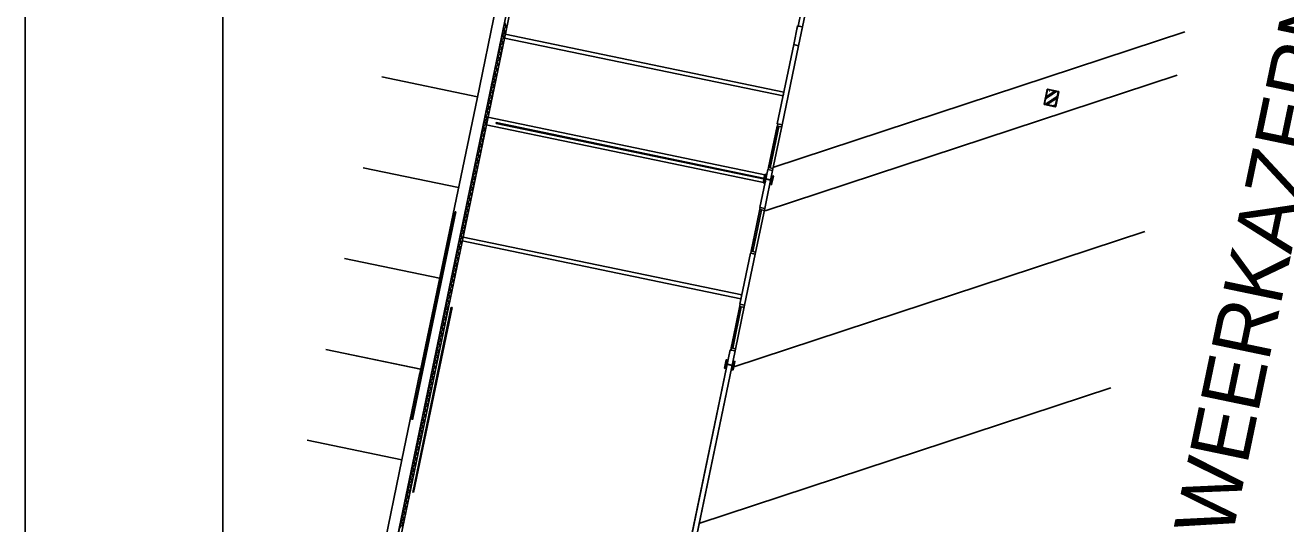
# Model space of a CAD drawing. Extents: x 81065 to 81486, y 452384 to 452681.
# Drawn here: x 81065.21 to 81097.13, y 452550.49 to 452563.13 of the extents above; entities that cross this region are included whole.
import ezdxf

# ---------------------------------------------------------------- set-up
doc = ezdxf.new("R2010")
doc.units = 0
for name, color, linetype in [('B-BH-AL-TOPOGRAFIE_STRAATNAAM-S', 7, 'Continuous'), ('B-BH-VH-KANTOPSLUITING-GV', 7, 'Continuous'), ('X-XX-AL-TEKENBLAD_KADER-G', 7, 'Continuous'), ('X-XX-AL-TEKENBLAD_KADER_AFSNIJMARKERING-G', 7, 'Continuous'), ('X-XX-AL-TEKENBLAD_VIEWPORT-G', 7, 'Continuous')]:
    doc.layers.add(name, color=color, linetype=linetype)

msp = doc.modelspace()

# ---------------------------------------------------------------- linework, layer by layer
at = {"layer": 'B-BH-VH-KANTOPSLUITING-GV'}
for p, q in [((81080.767, 452579.66), (81071.926, 452537.068)), ((81085.024, 452564.266), (81084.783, 452563.107)), ((81077.52, 452564.024), (81073.834, 452546.276)), ((81073.912, 452546.26), (81077.598, 452564.008)), ((81085.135, 452564.243), (81084.895, 452563.084)), ((81076.654, 452561.265), (81077.142, 452563.615)), ((81077.279, 452562.863), (81077.385, 452562.983)), ((81077.307, 452563.001), (81077.414, 452563.12)), ((81077.371, 452562.915), (81077.321, 452563.067)), ((81077.4, 452563.052), (81077.349, 452563.204)), ((81084.772, 452563.109), (81084.674, 452562.636)), ((81084.746, 452562.982), (81084.768, 452563.09)), ((81084.895, 452563.084), (81084.772, 452563.109)), ((81084.895, 452563.084), (81084.783, 452563.107)), ((81084.796, 452562.61), (81084.895, 452563.084)), ((81084.868, 452562.957), (81084.891, 452563.064)), ((81077.222, 452562.589), (81077.328, 452562.709)), ((81077.25, 452562.726), (81077.357, 452562.846)), ((81077.314, 452562.641), (81077.264, 452562.793)), ((81077.343, 452562.778), (81077.292, 452562.93)), ((81077.368, 452562.901), (81077.348, 452562.803)), ((81077.348, 452562.803), (81084.404, 452561.337)), ((81084.425, 452561.435), (81077.368, 452562.901)), ((81084.146, 452559.522), (81094.574, 452562.962)), ((81077.165, 452562.315), (81077.271, 452562.435)), ((81077.229, 452562.229), (81077.179, 452562.381)), ((81077.193, 452562.452), (81077.3, 452562.572)), ((81077.257, 452562.367), (81077.207, 452562.518)), ((81077.286, 452562.504), (81077.236, 452562.656)), ((81084.674, 452562.636), (81084.257, 452560.629)), ((81084.38, 452560.603), (81084.796, 452562.61)), ((81077.079, 452561.904), (81077.186, 452562.023)), ((81077.108, 452562.041), (81077.214, 452562.16)), ((81077.172, 452561.955), (81077.122, 452562.107)), ((81077.136, 452562.178), (81077.243, 452562.297)), ((81077.2, 452562.092), (81077.15, 452562.244)), ((81076.664, 452561.314), (81074.243, 452561.817)), ((81074.243, 452561.817), (81076.664, 452561.314)), ((81077.022, 452561.63), (81077.129, 452561.749)), ((81077.051, 452561.767), (81077.157, 452561.886)), ((81077.115, 452561.681), (81077.065, 452561.833)), ((81077.143, 452561.818), (81077.093, 452561.97)), ((81083.954, 452558.42), (81094.382, 452561.859)), ((81076.966, 452561.356), (81077.072, 452561.475)), ((81077.029, 452561.27), (81076.979, 452561.422)), ((81076.994, 452561.493), (81077.101, 452561.612)), ((81077.058, 452561.407), (81077.008, 452561.559)), ((81077.086, 452561.544), (81077.036, 452561.696)), ((81084.404, 452561.337), (81084.425, 452561.435)), ((81091.09, 452561.501), (81091.013, 452561.129)), ((81091.026, 452561.133), (81091.101, 452561.493)), ((81091.101, 452561.493), (81091.026, 452561.133)), ((81091.055, 452561.274), (81091.325, 452561.451)), ((81091.064, 452561.315), (81091.283, 452561.459)), ((81091.078, 452561.383), (81091.079, 452561.383)), ((81091.095, 452561.508), (81091.09, 452561.501)), ((81091.102, 452561.509), (81091.095, 452561.508)), ((81091.096, 452561.468), (81091.096, 452561.468)), ((81091.098, 452561.482), (81091.117, 452561.494)), ((81091.101, 452561.493), (81091.103, 452561.495)), ((81091.103, 452561.495), (81091.101, 452561.493)), ((81091.376, 452561.452), (81091.102, 452561.509)), ((81091.103, 452561.495), (81091.106, 452561.496)), ((81091.106, 452561.496), (81091.103, 452561.495)), ((81091.106, 452561.496), (81091.368, 452561.441)), ((81091.368, 452561.441), (81091.106, 452561.496)), ((81091.111, 452561.42), (81091.112, 452561.42)), ((81091.145, 452561.458), (81091.146, 452561.457)), ((81091.161, 452561.41), (81091.161, 452561.41)), ((81091.195, 452561.447), (81091.195, 452561.447)), ((81091.21, 452561.4), (81091.211, 452561.4)), ((81091.244, 452561.437), (81091.245, 452561.437)), ((81091.26, 452561.39), (81091.26, 452561.389)), ((81091.294, 452561.427), (81091.294, 452561.427)), ((81091.371, 452561.437), (81091.296, 452561.076)), ((81091.296, 452561.076), (81091.371, 452561.437)), ((81091.307, 452561.068), (81091.384, 452561.44)), ((81091.343, 452561.416), (81091.344, 452561.416)), ((81091.368, 452561.441), (81091.37, 452561.44)), ((81091.37, 452561.44), (81091.368, 452561.441)), ((81091.37, 452561.44), (81091.371, 452561.437)), ((81091.371, 452561.437), (81091.37, 452561.44)), ((81091.383, 452561.448), (81091.376, 452561.452)), ((81091.384, 452561.44), (81091.383, 452561.448)), ((81076.166, 452558.916), (81076.654, 452561.265)), ((81076.88, 452560.944), (81076.987, 452561.064)), ((81076.909, 452561.081), (81077.015, 452561.201)), ((81076.973, 452560.996), (81076.922, 452561.148)), ((81076.937, 452561.219), (81077.044, 452561.338)), ((81077.001, 452561.133), (81076.951, 452561.285)), ((81091.013, 452561.129), (81091.014, 452561.122)), ((81091.014, 452561.122), (81091.021, 452561.117)), ((81091.021, 452561.117), (81091.295, 452561.06)), ((81091.027, 452561.13), (81091.026, 452561.133)), ((81091.026, 452561.133), (81091.027, 452561.13)), ((81091.029, 452561.128), (81091.027, 452561.13)), ((81091.027, 452561.13), (81091.029, 452561.128)), ((81091.291, 452561.073), (81091.029, 452561.128)), ((81091.029, 452561.128), (81091.291, 452561.073)), ((81091.043, 452561.213), (81091.043, 452561.213)), ((81091.046, 452561.124), (81091.347, 452561.322)), ((81091.058, 452561.166), (81091.059, 452561.166)), ((81091.06, 452561.298), (81091.061, 452561.298)), ((81091.075, 452561.118), (81091.075, 452561.118)), ((81091.076, 452561.251), (81091.077, 452561.251)), ((81091.088, 452561.116), (81091.339, 452561.28)), ((81091.092, 452561.203), (81091.093, 452561.203)), ((81091.094, 452561.336), (81091.094, 452561.335)), ((81091.108, 452561.156), (81091.108, 452561.156)), ((81091.11, 452561.288), (81091.11, 452561.288)), ((81091.124, 452561.108), (81091.125, 452561.108)), ((81091.126, 452561.24), (81091.126, 452561.24)), ((81091.127, 452561.373), (81091.128, 452561.373)), ((81091.142, 452561.193), (81091.142, 452561.193)), ((81091.143, 452561.325), (81091.144, 452561.325)), ((81091.157, 452561.145), (81091.158, 452561.145)), ((81091.159, 452561.278), (81091.16, 452561.278)), ((81091.174, 452561.098), (81091.174, 452561.098)), ((81091.175, 452561.23), (81091.176, 452561.23)), ((81091.177, 452561.362), (81091.178, 452561.362)), ((81091.191, 452561.183), (81091.192, 452561.182)), ((81091.193, 452561.315), (81091.193, 452561.315)), ((81091.207, 452561.135), (81091.208, 452561.135)), ((81091.209, 452561.267), (81091.21, 452561.267)), ((81091.223, 452561.088), (81091.224, 452561.087)), ((81091.225, 452561.22), (81091.225, 452561.22)), ((81091.227, 452561.352), (81091.227, 452561.352)), ((81091.241, 452561.172), (81091.241, 452561.172)), ((81091.242, 452561.305), (81091.243, 452561.305)), ((81091.254, 452561.081), (81091.304, 452561.114)), ((81091.257, 452561.125), (81091.257, 452561.125)), ((81091.258, 452561.257), (81091.259, 452561.257)), ((81091.273, 452561.077), (81091.273, 452561.077)), ((81091.274, 452561.21), (81091.275, 452561.21)), ((81091.276, 452561.342), (81091.277, 452561.342)), ((81091.29, 452561.162), (81091.291, 452561.162)), ((81091.294, 452561.074), (81091.291, 452561.073)), ((81091.291, 452561.073), (81091.294, 452561.074)), ((81091.292, 452561.294), (81091.292, 452561.294)), ((81091.296, 452561.076), (81091.294, 452561.074)), ((81091.294, 452561.074), (81091.296, 452561.076)), ((81091.302, 452561.062), (81091.307, 452561.068)), ((81091.308, 452561.247), (81091.309, 452561.247)), ((81091.309, 452561.379), (81091.31, 452561.379)), ((81091.326, 452561.332), (81091.326, 452561.331)), ((81076.823, 452560.67), (81076.93, 452560.79)), ((81076.852, 452560.807), (81076.958, 452560.927)), ((81076.916, 452560.722), (81076.865, 452560.874)), ((81076.931, 452560.795), (81076.89, 452560.6)), ((81076.944, 452560.859), (81076.894, 452561.011)), ((81083.987, 452559.33), (81076.931, 452560.795)), ((81091.295, 452561.06), (81091.302, 452561.062)), ((81076.766, 452560.396), (81076.873, 452560.516)), ((81076.83, 452560.31), (81076.78, 452560.462)), ((81076.795, 452560.533), (81076.901, 452560.653)), ((81076.859, 452560.447), (81076.809, 452560.599)), ((81076.887, 452560.585), (81076.837, 452560.737)), ((81076.89, 452560.6), (81083.947, 452559.134)), ((81077.14, 452560.65), (81077.138, 452560.64)), ((81077.138, 452560.64), (81083.94, 452559.228)), ((81077.142, 452560.66), (81077.14, 452560.65)), ((81083.942, 452559.237), (81077.14, 452560.65)), ((81077.14, 452560.65), (81083.942, 452559.237)), ((81083.944, 452559.247), (81077.142, 452560.66)), ((81084.268, 452560.627), (81084.027, 452559.467)), ((81084.257, 452560.573), (81084.038, 452559.521)), ((81084.078, 452559.513), (81084.296, 452560.565)), ((81084.38, 452560.603), (81084.139, 452559.444)), ((81084.38, 452560.603), (81084.257, 452560.629)), ((81084.257, 452560.573), (81084.368, 452560.55)), ((81084.296, 452560.565), (81084.257, 452560.573)), ((81084.38, 452560.603), (81084.268, 452560.627)), ((81076.709, 452560.122), (81076.816, 452560.241)), ((81076.773, 452560.036), (81076.723, 452560.188)), ((81076.738, 452560.259), (81076.844, 452560.378)), ((81076.802, 452560.173), (81076.752, 452560.325)), ((81076.624, 452559.711), (81076.73, 452559.83)), ((81076.652, 452559.848), (81076.759, 452559.967)), ((81076.716, 452559.762), (81076.666, 452559.914)), ((81076.681, 452559.985), (81076.787, 452560.104)), ((81076.745, 452559.899), (81076.695, 452560.051)), ((81076.186, 452559.013), (81073.77, 452559.515)), ((81073.77, 452559.515), (81076.186, 452559.013)), ((81076.567, 452559.437), (81076.674, 452559.556)), ((81076.631, 452559.351), (81076.581, 452559.503)), ((81076.595, 452559.574), (81076.702, 452559.693)), ((81076.659, 452559.488), (81076.609, 452559.64)), ((81076.688, 452559.625), (81076.638, 452559.777)), ((81084.016, 452559.47), (81083.817, 452558.51)), ((81084.139, 452559.444), (81084.016, 452559.47)), ((81084.139, 452559.444), (81084.027, 452559.467)), ((81084.038, 452559.521), (81084.15, 452559.498)), ((81084.038, 452559.521), (81084.078, 452559.513)), ((81076.51, 452559.162), (81076.617, 452559.282)), ((81076.574, 452559.077), (81076.524, 452559.229)), ((81076.539, 452559.3), (81076.645, 452559.419)), ((81076.602, 452559.214), (81076.552, 452559.366)), ((81083.943, 452559.349), (81083.899, 452559.134)), ((81083.914, 452559.131), (81083.936, 452559.234)), ((81083.936, 452559.234), (81084.12, 452559.195)), ((81083.938, 452559.243), (81083.959, 452559.346)), ((81084.122, 452559.205), (81083.938, 452559.243)), ((81083.939, 452558.484), (81084.139, 452559.444)), ((81083.94, 452559.228), (81083.942, 452559.237)), ((81083.942, 452559.237), (81083.944, 452559.247)), ((81083.959, 452559.346), (81083.943, 452559.349)), ((81083.947, 452559.134), (81083.987, 452559.33)), ((81084.12, 452559.195), (81084.098, 452559.092)), ((81084.114, 452559.089), (81084.159, 452559.305)), ((81084.143, 452559.308), (81084.122, 452559.205)), ((81084.159, 452559.305), (81084.143, 452559.308)), ((81075.678, 452556.566), (81076.166, 452558.916)), ((81076.425, 452558.751), (81076.531, 452558.871)), ((81076.453, 452558.888), (81076.56, 452559.008)), ((81076.517, 452558.803), (81076.467, 452558.955)), ((81076.482, 452559.025), (81076.588, 452559.145)), ((81076.546, 452558.94), (81076.495, 452559.092)), ((81083.899, 452559.134), (81083.914, 452559.131)), ((81084.098, 452559.092), (81084.114, 452559.089)), ((81076.368, 452558.477), (81076.474, 452558.596)), ((81076.432, 452558.391), (81076.381, 452558.543)), ((81076.396, 452558.614), (81076.503, 452558.734)), ((81076.46, 452558.528), (81076.41, 452558.68)), ((81076.489, 452558.666), (81076.438, 452558.817)), ((81083.939, 452558.484), (81083.817, 452558.51)), ((81076.097, 452558.402), (81075.003, 452553.133)), ((81075.013, 452553.131), (81076.107, 452558.4)), ((81076.107, 452558.4), (81075.013, 452553.131)), ((81075.022, 452553.129), (81076.117, 452558.398)), ((81076.107, 452558.4), (81076.097, 452558.402)), ((81076.117, 452558.398), (81076.107, 452558.4)), ((81076.311, 452558.203), (81076.417, 452558.322)), ((81076.375, 452558.117), (81076.325, 452558.269)), ((81076.339, 452558.34), (81076.446, 452558.459)), ((81076.403, 452558.254), (81076.353, 452558.406)), ((81083.828, 452558.507), (81083.587, 452557.348)), ((81083.817, 452558.454), (81083.598, 452557.402)), ((81083.637, 452557.394), (81083.856, 452558.445)), ((81083.939, 452558.484), (81083.699, 452557.325)), ((81083.817, 452558.454), (81083.928, 452558.43)), ((81083.856, 452558.445), (81083.817, 452558.454)), ((81083.939, 452558.484), (81083.828, 452558.507)), ((81076.225, 452557.792), (81076.332, 452557.911)), ((81076.254, 452557.929), (81076.36, 452558.048)), ((81076.318, 452557.843), (81076.268, 452557.995)), ((81076.282, 452558.066), (81076.389, 452558.185)), ((81076.346, 452557.98), (81076.296, 452558.132)), ((81083.132, 452554.463), (81093.56, 452557.902)), ((81076.168, 452557.518), (81076.275, 452557.637)), ((81076.232, 452557.432), (81076.182, 452557.584)), ((81076.197, 452557.655), (81076.303, 452557.774)), ((81076.261, 452557.569), (81076.211, 452557.721)), ((81076.289, 452557.706), (81076.239, 452557.858)), ((81076.301, 452557.76), (81076.28, 452557.662)), ((81076.28, 452557.662), (81083.337, 452556.197)), ((81083.357, 452556.295), (81076.301, 452557.76)), ((81076.112, 452557.243), (81076.218, 452557.363)), ((81076.175, 452557.158), (81076.125, 452557.31)), ((81076.14, 452557.38), (81076.246, 452557.5)), ((81076.204, 452557.295), (81076.154, 452557.447)), ((81083.576, 452557.35), (81083.307, 452556.056)), ((81083.43, 452556.03), (81083.699, 452557.325)), ((81083.699, 452557.325), (81083.576, 452557.35)), ((81083.699, 452557.325), (81083.587, 452557.348)), ((81083.598, 452557.402), (81083.71, 452557.379)), ((81083.598, 452557.402), (81083.637, 452557.394)), ((81075.708, 452556.713), (81073.298, 452557.214)), ((81073.298, 452557.214), (81075.708, 452556.713)), ((81076.026, 452556.832), (81076.133, 452556.952)), ((81076.055, 452556.969), (81076.161, 452557.089)), ((81076.118, 452556.884), (81076.068, 452557.035)), ((81076.083, 452557.106), (81076.19, 452557.226)), ((81076.147, 452557.021), (81076.097, 452557.173)), ((81075.969, 452556.558), (81076.076, 452556.677)), ((81076.033, 452556.472), (81075.983, 452556.624)), ((81075.998, 452556.695), (81076.104, 452556.814)), ((81076.062, 452556.609), (81076.011, 452556.761)), ((81076.09, 452556.746), (81076.04, 452556.898)), ((81075.19, 452554.216), (81075.678, 452556.566)), ((81075.912, 452556.284), (81076.019, 452556.403)), ((81075.976, 452556.198), (81075.926, 452556.35)), ((81075.941, 452556.421), (81076.047, 452556.54)), ((81076.005, 452556.335), (81075.954, 452556.487)), ((81083.337, 452556.197), (81083.357, 452556.295)), ((81076.002, 452555.978), (81075.028, 452551.287)), ((81075.037, 452551.285), (81076.012, 452555.976)), ((81076.011, 452555.975), (81075.037, 452551.285)), ((81075.047, 452551.283), (81076.021, 452555.973)), ((81075.827, 452555.873), (81075.933, 452555.992)), ((81075.855, 452556.01), (81075.962, 452556.129)), ((81075.919, 452555.924), (81075.869, 452556.076)), ((81075.884, 452556.147), (81075.99, 452556.266)), ((81075.948, 452556.061), (81075.898, 452556.213)), ((81076.012, 452555.976), (81076.002, 452555.978)), ((81076.021, 452555.973), (81076.011, 452555.975)), ((81083.318, 452556.054), (81083.077, 452554.894)), ((81083.307, 452556), (81083.089, 452554.948)), ((81083.128, 452554.94), (81083.346, 452555.992)), ((81083.43, 452556.03), (81083.189, 452554.871)), ((81083.43, 452556.03), (81083.307, 452556.056)), ((81083.307, 452556), (81083.419, 452555.977)), ((81083.346, 452555.992), (81083.307, 452556)), ((81083.43, 452556.03), (81083.318, 452556.054)), ((81075.77, 452555.598), (81075.876, 452555.718)), ((81075.834, 452555.513), (81075.784, 452555.665)), ((81075.798, 452555.736), (81075.905, 452555.855)), ((81075.862, 452555.65), (81075.812, 452555.802)), ((81075.891, 452555.787), (81075.841, 452555.939)), ((81075.713, 452555.324), (81075.819, 452555.444)), ((81075.777, 452555.239), (81075.727, 452555.391)), ((81075.741, 452555.461), (81075.848, 452555.581)), ((81075.805, 452555.376), (81075.755, 452555.528)), ((81075.628, 452554.913), (81075.734, 452555.033)), ((81075.656, 452555.05), (81075.763, 452555.17)), ((81075.72, 452554.964), (81075.67, 452555.116)), ((81075.685, 452555.187), (81075.791, 452555.307)), ((81075.748, 452555.102), (81075.698, 452555.254)), ((81075.222, 452554.413), (81072.825, 452554.911)), ((81072.825, 452554.911), (81075.23, 452554.411)), ((81075.571, 452554.639), (81075.677, 452554.758)), ((81075.635, 452554.553), (81075.584, 452554.705)), ((81075.599, 452554.776), (81075.706, 452554.895)), ((81075.663, 452554.69), (81075.613, 452554.842)), ((81075.691, 452554.827), (81075.641, 452554.979)), ((81083.067, 452554.897), (81081.355, 452546.652)), ((81081.477, 452546.627), (81083.189, 452554.871)), ((81083.189, 452554.871), (81083.067, 452554.897)), ((81083.189, 452554.871), (81083.077, 452554.894)), ((81083.089, 452554.948), (81083.2, 452554.925)), ((81083.089, 452554.948), (81083.128, 452554.94)), ((81075.514, 452554.365), (81075.62, 452554.484)), ((81075.578, 452554.279), (81075.527, 452554.431)), ((81075.542, 452554.502), (81075.649, 452554.621)), ((81075.606, 452554.416), (81075.556, 452554.568)), ((81082.967, 452554.65), (81082.923, 452554.434)), ((81082.923, 452554.434), (81082.938, 452554.431)), ((81082.938, 452554.431), (81082.96, 452554.534)), ((81082.96, 452554.534), (81083.144, 452554.496)), ((81082.962, 452554.543), (81082.983, 452554.646)), ((81083.146, 452554.505), (81082.962, 452554.543)), ((81082.983, 452554.646), (81082.967, 452554.65)), ((81083.144, 452554.496), (81083.122, 452554.393)), ((81083.122, 452554.393), (81083.138, 452554.389)), ((81083.138, 452554.389), (81083.183, 452554.605)), ((81083.167, 452554.608), (81083.146, 452554.505)), ((81083.183, 452554.605), (81083.167, 452554.608)), ((81074.752, 452552.111), (81075.21, 452554.314)), ((81075.428, 452553.954), (81075.535, 452554.073)), ((81075.457, 452554.091), (81075.563, 452554.21)), ((81075.521, 452554.005), (81075.471, 452554.157)), ((81075.485, 452554.228), (81075.592, 452554.347)), ((81075.549, 452554.142), (81075.499, 452554.294)), ((81075.371, 452553.679), (81075.478, 452553.799)), ((81075.435, 452553.594), (81075.385, 452553.746)), ((81075.4, 452553.817), (81075.506, 452553.936)), ((81075.464, 452553.731), (81075.414, 452553.883)), ((81075.492, 452553.868), (81075.442, 452554.02)), ((81082.271, 452550.496), (81092.699, 452553.935)), ((81075.314, 452553.405), (81075.421, 452553.525)), ((81075.378, 452553.32), (81075.328, 452553.472)), ((81075.343, 452553.542), (81075.449, 452553.662)), ((81075.407, 452553.457), (81075.357, 452553.609)), ((81075.229, 452552.994), (81075.336, 452553.113)), ((81075.257, 452553.131), (81075.364, 452553.251)), ((81075.321, 452553.045), (81075.271, 452553.197)), ((81075.286, 452553.268), (81075.392, 452553.388)), ((81075.35, 452553.183), (81075.3, 452553.334)), ((81075.172, 452552.72), (81075.279, 452552.839)), ((81075.236, 452552.634), (81075.186, 452552.786)), ((81075.201, 452552.857), (81075.307, 452552.976)), ((81075.264, 452552.771), (81075.214, 452552.923)), ((81075.293, 452552.908), (81075.243, 452553.06)), ((81072.352, 452552.61), (81074.752, 452552.111)), ((81074.752, 452552.111), (81072.352, 452552.61)), ((81075.115, 452552.446), (81075.222, 452552.565)), ((81075.179, 452552.36), (81075.129, 452552.512)), ((81075.144, 452552.583), (81075.25, 452552.702)), ((81075.208, 452552.497), (81075.157, 452552.649)), ((81075.03, 452552.035), (81075.136, 452552.154)), ((81075.058, 452552.172), (81075.165, 452552.291)), ((81075.122, 452552.086), (81075.072, 452552.238)), ((81075.087, 452552.309), (81075.193, 452552.428)), ((81075.151, 452552.223), (81075.1, 452552.375)), ((81074.254, 452549.712), (81074.752, 452552.111)), ((81074.973, 452551.76), (81075.079, 452551.88)), ((81075.037, 452551.675), (81074.987, 452551.827)), ((81075.001, 452551.897), (81075.108, 452552.017)), ((81075.065, 452551.812), (81075.015, 452551.964)), ((81075.094, 452551.949), (81075.044, 452552.101)), ((81074.916, 452551.486), (81075.022, 452551.606)), ((81074.98, 452551.401), (81074.93, 452551.552)), ((81074.944, 452551.623), (81075.051, 452551.743)), ((81075.008, 452551.538), (81074.958, 452551.69)), ((81074.83, 452551.075), (81074.937, 452551.194)), ((81074.859, 452551.212), (81074.965, 452551.331)), ((81074.923, 452551.126), (81074.873, 452551.278)), ((81074.887, 452551.349), (81074.994, 452551.469)), ((81074.951, 452551.263), (81074.901, 452551.415)), ((81074.774, 452550.801), (81074.88, 452550.92)), ((81074.837, 452550.715), (81074.787, 452550.867)), ((81074.802, 452550.938), (81074.909, 452551.057)), ((81074.866, 452550.852), (81074.816, 452551.004)), ((81074.894, 452550.989), (81074.844, 452551.141)), ((81074.717, 452550.527), (81074.823, 452550.646)), ((81074.781, 452550.441), (81074.73, 452550.593)), ((81074.745, 452550.664), (81074.852, 452550.783)), ((81074.809, 452550.578), (81074.759, 452550.73)), ((81074.688, 452550.39), (81074.795, 452550.509))]:
    msp.add_line(p, q, dxfattribs=at)
for points in [[(81084.674, 452562.636), (81084.772, 452563.109), (81084.895, 452563.084), (81084.796, 452562.61), (81084.674, 452562.636)], [(81077.348, 452562.803), (81077.368, 452562.901), (81084.425, 452561.435), (81084.404, 452561.337), (81077.348, 452562.803)], [(81084.257, 452560.629), (81084.674, 452562.636), (81084.796, 452562.61), (81084.38, 452560.603), (81084.257, 452560.629)], [(81076.89, 452560.6), (81076.931, 452560.795), (81083.987, 452559.33), (81083.947, 452559.134), (81076.89, 452560.6)], [(81083.817, 452558.51), (81084.016, 452559.47), (81084.139, 452559.444), (81083.939, 452558.484), (81083.817, 452558.51)], [(81083.899, 452559.134), (81083.943, 452559.349), (81083.959, 452559.346), (81083.938, 452559.243), (81084.122, 452559.205), (81084.143, 452559.308), (81084.159, 452559.305), (81084.114, 452559.089), (81084.098, 452559.092), (81084.12, 452559.195), (81083.936, 452559.234), (81083.914, 452559.131), (81083.899, 452559.134)], [(81076.28, 452557.662), (81076.301, 452557.76), (81083.357, 452556.295), (81083.337, 452556.197), (81076.28, 452557.662)], [(81083.307, 452556.056), (81083.576, 452557.35), (81083.699, 452557.325), (81083.43, 452556.03), (81083.307, 452556.056)], [(81081.355, 452546.652), (81083.067, 452554.897), (81083.189, 452554.871), (81081.477, 452546.627), (81081.355, 452546.652)], [(81082.923, 452554.434), (81082.967, 452554.65), (81082.983, 452554.646), (81082.962, 452554.543), (81083.146, 452554.505), (81083.167, 452554.608), (81083.183, 452554.605), (81083.138, 452554.389), (81083.122, 452554.393), (81083.144, 452554.496), (81082.96, 452554.534), (81082.938, 452554.431), (81082.923, 452554.434)]]:
    msp.add_lwpolyline(points, dxfattribs=at)
at = {"layer": 'X-XX-AL-TEKENBLAD_KADER-G'}
msp.add_lwpolyline([(81480.708, 452388.532), (81070.22, 452388.532), (81070.22, 452675.532), (81480.708, 452675.532)], close=True, dxfattribs=at)
at = {"layer": 'X-XX-AL-TEKENBLAD_KADER_AFSNIJMARKERING-G'}
msp.add_lwpolyline([(81485.714, 452680.532), (81065.214, 452680.532), (81065.214, 452383.532), (81485.714, 452383.532)], close=True, dxfattribs=at)
at = {"layer": 'X-XX-AL-TEKENBLAD_VIEWPORT-G'}
msp.add_lwpolyline([(81070.22, 452388.532), (81480.708, 452388.532), (81480.708, 452675.532), (81070.22, 452675.532)], close=True, dxfattribs=at)

# ---------------------------------------------------------------- texts
at = {"layer": 'B-BH-AL-TOPOGRAFIE_STRAATNAAM-S'}
msp.add_text('BRANDWEERKAZERNE', height=1.5, rotation=78.2165, dxfattribs=at).set_placement((81094.33, 452543.227))

doc.saveas('drawing.dxf')
